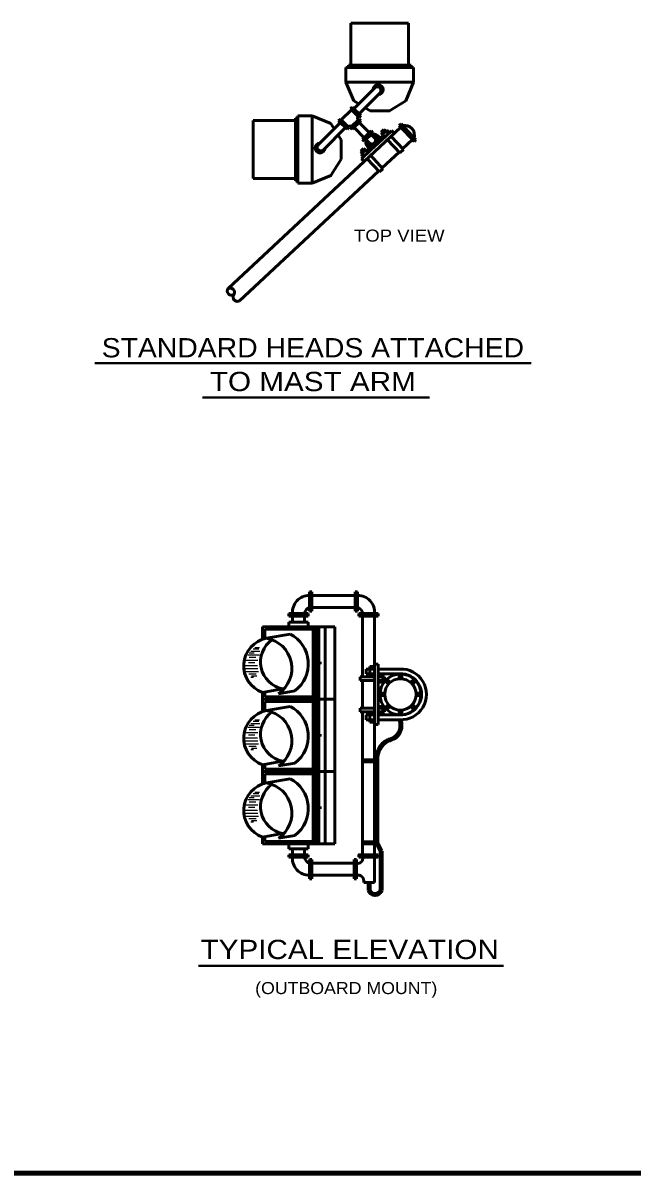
# Model space of a CAD drawing. Extents: x -370 to 486, y -203 to 341.
# Drawn here: x -43.9 to 107.7, y -191.2 to 95.1 of the extents above; entities that cross this region are included whole.
import ezdxf
from ezdxf.enums import TextEntityAlignment as Align

# ---------------------------------------------------------------- set-up
doc = ezdxf.new("R2010")
doc.units = 0
doc.header["$LTSCALE"] = 0.96
doc.layers.add('1', color=7, linetype='Continuous', lineweight=53)

msp = doc.modelspace()

# ---------------------------------------------------------------- linework, layer by layer
at = {"layer": '1'}
for p, q in [((37.6829, 95.0558), (37.6829, 84.5558)), ((37.6829, 95.0558), (52.0829, 95.0558)), ((52.0829, 95.0558), (52.0829, 84.5558)), ((36.4829, 83.9558), (53.2829, 83.9558)), ((36.4829, 83.9558), (36.4829, 80.3558)), ((37.0829, 84.5558), (52.6829, 84.5558)), ((37.0829, 84.5558), (37.0829, 83.9558)), ((52.6829, 84.5558), (52.6829, 83.9558)), ((53.2829, 83.9558), (53.2829, 80.3558)), ((36.4829, 80.3558), (53.2829, 80.3558)), ((38.4123, 75.6994), (36.4829, 80.3558)), ((51.3535, 75.6994), (53.2829, 80.3558)), ((43.6829, 78.9279), (38.4695, 73.688)), ((44.9587, 77.6586), (39.7453, 72.4184)), ((39.6816, 74.9063), (38.4123, 75.6994)), ((24.4829, 55.1558), (24.4829, 71.9558)), ((24.4829, 71.9558), (28.0829, 71.9558)), ((28.0829, 55.1558), (28.0829, 71.9558)), ((32.7392, 70.0263), (28.0829, 71.9558)), ((37.8336, 73.4744), (35.2946, 70.9223)), ((38.044, 74.1114), (37.6209, 73.686)), ((39.7474, 71.5699), (37.6209, 73.686)), ((40.1706, 71.9953), (38.044, 74.1114)), ((40.1706, 71.9953), (39.7474, 71.5699)), ((42.4829, 73.1558), (41.2472, 73.928)), ((13.3828, 56.3557), (13.3829, 70.7558)), ((13.3829, 70.7558), (23.8829, 70.7558)), ((23.8829, 55.7558), (23.8828, 71.3557)), ((23.8828, 71.3557), (24.4829, 71.3557)), ((35.0843, 70.2853), (29.5829, 64.7558)), ((36.36, 69.0156), (30.8587, 63.4862)), ((33.5445, 68.7377), (32.7392, 70.0263)), ((35.0817, 71.1342), (34.6585, 70.709)), ((36.7849, 68.5928), (34.6585, 70.709)), ((37.2081, 69.0181), (35.0817, 71.1342)), ((36.7849, 68.5928), (37.2081, 69.0181)), ((39.7485, 71.1458), (37.6325, 69.0189)), ((37.6325, 69.0189), (38.0578, 68.5958)), ((40.1738, 70.7227), (38.0578, 68.5958)), ((38.4809, 69.0211), (41.033, 66.4821)), ((39.7485, 71.1458), (40.1738, 70.7227)), ((39.7506, 70.2975), (42.3028, 67.7585)), ((50.1533, 69.0996), (41.0165, 60.5794)), ((50.183, 69.9476), (49.7442, 69.5384)), ((49.7442, 69.5384), (53.4269, 65.589)), ((50.183, 69.9476), (53.8657, 65.9982)), ((35.2829, 65.9558), (34.524, 67.1702)), ((35.2829, 61.1558), (35.2829, 65.9558)), ((42.7259, 68.1836), (40.6099, 66.0567)), ((40.6099, 66.0567), (41.0352, 65.6336)), ((43.1512, 67.7605), (41.0352, 65.6336)), ((41.4583, 66.0589), (42.345, 65.1769)), ((42.7259, 68.1836), (43.1512, 67.7605)), ((42.7282, 67.3353), (43.5787, 66.4892)), ((44.0623, 66.5011), (44.9781, 65.5902)), ((44.4379, 66.9738), (45.4172, 65.9997)), ((45.2662, 67.9102), (45.9243, 68.5241)), ((45.2662, 67.9102), (45.6755, 67.4712)), ((45.3463, 67.1644), (45.9601, 66.5061)), ((46.6628, 68.3919), (45.3464, 67.1643)), ((45.4708, 67.6909), (46.1289, 68.3048)), ((45.5657, 67.369), (46.1796, 66.7106)), ((45.5877, 68.0053), (45.8072, 68.21)), ((45.7924, 67.7861), (46.0119, 67.9907)), ((45.9243, 68.5241), (46.3337, 68.085)), ((46.4433, 68.1874), (47.0572, 67.529)), ((46.6628, 68.3919), (47.2766, 67.7336)), ((46.8362, 66.0064), (49.905, 62.715)), ((47.7139, 66.8248), (50.7826, 63.5334)), ((47.8412, 68.2601), (48.5243, 67.5805)), ((53.0178, 66.0278), (50.5781, 63.7528)), ((53.8657, 65.9982), (53.4269, 65.589)), ((40.182, 63.1691), (40.8401, 63.783)), ((40.182, 63.1691), (40.5913, 62.7301)), ((41.5786, 63.6508), (40.2622, 62.4232)), ((42.7085, 63.4738), (40.3598, 61.2836)), ((40.3866, 62.9498), (41.0447, 63.5637)), ((40.5035, 63.2642), (40.723, 63.4689)), ((40.7082, 63.045), (40.9277, 63.2496)), ((40.8401, 63.783), (41.2495, 63.3439)), ((41.3591, 63.4463), (41.973, 62.7879)), ((41.5786, 63.6508), (42.1924, 62.9925)), ((41.8508, 64.3269), (42.7085, 63.4738)), ((42.274, 64.7522), (43.1249, 63.9058)), ((50.7826, 63.5334), (49.905, 62.715)), ((41.0166, 60.5793), (7.1499, 28.9979)), ((40.2621, 62.4233), (40.8759, 61.765)), ((40.3474, 61.272), (41.0306, 60.5924)), ((40.4815, 62.6279), (41.0954, 61.9695)), ((41.752, 61.2653), (44.8208, 57.9739)), ((42.6296, 62.0836), (45.6984, 58.7922)), ((49.7005, 62.9343), (45.4939, 59.0116)), ((44.6163, 58.1933), (10.0142, 25.9263)), ((45.6984, 58.7922), (44.8208, 57.9739)), ((13.3828, 56.3557), (23.8828, 56.3557)), ((23.8829, 55.7558), (24.4829, 55.7557)), ((24.4829, 55.1558), (28.0829, 55.1558)), ((27.3912, -51.3342), (27.3912, -46.5342)), ((27.3912, -46.5342), (27.9912, -46.5342)), ((27.9912, -51.3342), (27.9912, -46.5342)), ((27.9912, -47.4342), (38.7912, -47.4342)), ((38.7912, -51.3342), (38.7912, -46.5342)), ((38.7912, -51.3342), (38.7912, -46.5342)), ((38.7912, -46.5342), (39.3912, -46.5342)), ((39.3912, -51.3342), (39.3912, -46.5342)), ((27.3912, -51.3342), (27.9912, -51.3342)), ((27.9912, -50.4342), (38.7912, -50.4342)), ((38.7912, -51.3342), (39.3912, -51.3342)), ((22.2912, -51.9342), (27.0912, -51.9342)), ((22.2912, -51.9342), (22.2912, -52.5342)), ((22.2912, -52.5342), (27.0912, -52.5342)), ((22.2912, -54.0342), (27.0912, -54.0342)), ((22.2912, -54.0342), (22.2912, -55.2342)), ((23.1912, -52.5342), (23.1912, -54.0342)), ((26.1912, -52.5342), (26.1912, -54.0342)), ((27.0912, -51.9342), (27.0912, -52.5342)), ((27.0912, -54.0342), (27.0912, -55.2342)), ((44.4912, -51.9342), (39.6912, -51.9342)), ((39.6912, -51.9342), (39.6912, -52.5342)), ((44.4912, -52.5342), (39.6912, -52.5342)), ((40.5912, -52.5342), (40.5912, -67.6542)), ((44.4912, -51.9342), (44.4912, -52.5342)), ((15.6912, -55.2342), (33.6912, -55.2342)), ((15.6912, -55.2342), (15.6912, -58.3133)), ((16.2912, -55.8342), (28.8912, -55.8342)), ((16.2912, -55.8342), (16.2912, -58.153)), ((22.5912, -57.0342), (16.6824, -58.0761)), ((28.2912, -55.8342), (28.2912, -72.6342)), ((28.8912, -55.8342), (28.8912, -72.6342)), ((31.2912, -55.2342), (31.2912, -109.2342)), ((33.6912, -55.2342), (33.6912, -109.2342)), ((30.0912, -63.9342), (28.8912, -63.9342)), ((30.0912, -64.5342), (28.8912, -64.5342)), ((30.0912, -63.9342), (30.0912, -64.5342)), ((41.4912, -65.7342), (41.4912, -66.9342)), ((41.4912, -65.7342), (43.5912, -65.7342)), ((42.3912, -65.1342), (43.5912, -65.1342)), ((42.3912, -65.1342), (42.3912, -67.5342)), ((43.5912, -64.5342), (44.4912, -64.5342)), ((44.4912, -64.5342), (44.4912, -79.5342)), ((44.4912, -65.7342), (49.8912, -65.7342)), ((39.9912, -67.6542), (43.5912, -67.6542)), ((39.9912, -67.6542), (39.9912, -68.6142)), ((39.9912, -68.6142), (43.5912, -68.6142)), ((40.5912, -68.6142), (40.5912, -75.4542)), ((41.4912, -66.9342), (43.5912, -66.9342)), ((42.3912, -67.5342), (43.5912, -67.5342)), ((44.4912, -66.9342), (49.8912, -66.9342)), ((44.4912, -67.2342), (45.6912, -67.2342)), ((44.4912, -67.6542), (46.1112, -67.6542)), ((44.4912, -68.6142), (46.1112, -68.6142)), ((45.6912, -67.2342), (45.6912, -69.0342)), ((46.1112, -67.6542), (46.1112, -68.6142)), ((47.0679, -69.4743), (46.2421, -68.6486)), ((47.4922, -69.05), (46.6664, -68.2243)), ((49.7516, -68.133), (49.7516, -66.9596)), ((50.3516, -68.133), (50.3516, -66.9596)), ((52.5785, -69.07), (53.4294, -68.2238)), ((53.0016, -69.4955), (53.8525, -68.6493)), ((20.6964, -70.6569), (15.6912, -71.5394)), ((15.6912, -73.2342), (15.6912, -71.5394)), ((16.2912, -72.6342), (16.2912, -71.4336)), ((23.7912, -71.1342), (19.655, -71.8635)), ((44.4912, -69.0342), (45.6912, -69.0342)), ((15.6912, -73.2342), (33.6912, -73.2342)), ((15.6912, -73.2342), (15.6912, -76.3442)), ((16.2912, -72.6342), (28.8912, -72.6342)), ((16.2912, -73.8342), (28.8912, -73.8342)), ((16.2912, -73.8342), (16.2912, -76.1633)), ((28.2912, -73.8342), (28.2912, -90.6342)), ((28.8912, -73.8342), (28.8912, -90.6342)), ((44.9517, -71.7342), (46.1248, -71.7342)), ((44.9517, -72.3342), (46.1248, -72.3342)), ((53.9248, -71.7342), (55.1515, -71.7342)), ((53.9248, -72.3342), (55.1515, -72.3342)), ((22.5912, -75.0342), (16.6824, -76.0761)), ((39.9912, -75.4542), (43.5912, -75.4542)), ((39.9912, -75.4542), (39.9912, -76.4142)), ((39.9912, -76.4142), (43.5912, -76.4142)), ((40.5912, -76.4142), (40.5912, -111.9598)), ((41.4912, -77.1342), (41.4912, -78.3342)), ((41.4912, -77.1342), (43.5912, -77.1342)), ((42.3912, -76.5342), (42.3912, -78.9342)), ((42.3912, -76.5342), (43.5912, -76.5342)), ((44.4912, -75.0342), (45.6912, -75.0342)), ((44.4912, -75.4542), (46.1112, -75.4542)), ((44.4912, -76.4142), (46.1112, -76.4142)), ((44.4912, -76.8342), (45.6912, -76.8342)), ((44.4912, -77.1342), (49.8912, -77.1342)), ((45.6912, -75.0342), (45.6912, -76.8342)), ((46.1112, -75.4542), (46.1112, -76.4142)), ((46.1972, -75.4162), (47.0479, -74.5702)), ((46.6203, -75.8417), (47.471, -74.9957)), ((49.7516, -77.1596), (49.7516, -75.9328)), ((50.3516, -77.1596), (50.3516, -75.9328)), ((53.4595, -75.8641), (52.5841, -74.989)), ((53.8836, -75.4398), (53.0082, -74.5647)), ((41.4912, -78.3342), (43.5912, -78.3342)), ((42.3912, -78.9342), (43.5912, -78.9342)), ((43.5912, -79.5342), (44.4912, -79.5342)), ((44.4912, -78.3342), (49.8912, -78.3342)), ((30.0912, -81.9342), (28.8912, -81.9342)), ((30.0912, -82.5342), (28.8912, -82.5342)), ((30.0912, -81.9342), (30.0912, -82.5342)), ((20.6964, -88.6569), (15.6912, -89.5394)), ((15.6912, -91.2342), (15.6912, -89.5394)), ((15.6912, -91.2342), (33.6912, -91.2342)), ((15.6912, -91.2342), (15.6912, -94.3442)), ((16.2912, -90.6342), (16.2912, -89.4336)), ((16.2912, -90.6342), (28.8912, -90.6342)), ((23.7912, -89.1342), (19.655, -89.8635)), ((16.2912, -91.8342), (28.8912, -91.8342)), ((16.2912, -91.8342), (16.2912, -94.1633)), ((22.5912, -93.0342), (16.6824, -94.0761)), ((28.2912, -91.8342), (28.2912, -108.6342)), ((28.8912, -91.8342), (28.8912, -108.6342)), ((30.0912, -99.9342), (28.8912, -99.9342)), ((30.0912, -99.9342), (30.0912, -100.5342)), ((30.0912, -100.5342), (28.8912, -100.5342)), ((20.6964, -106.6569), (15.6912, -107.5394)), ((15.6912, -109.2342), (15.6912, -107.5394)), ((16.2912, -108.6342), (16.2912, -107.4336)), ((16.2912, -108.6342), (28.8912, -108.6342)), ((23.7912, -107.1342), (19.655, -107.8635)), ((15.6912, -109.2342), (33.6912, -109.2342)), ((22.2912, -110.4594), (22.2912, -109.2594)), ((22.2912, -110.4594), (27.0912, -110.4594)), ((23.1912, -111.9594), (23.1912, -110.4594)), ((26.1912, -111.9594), (26.1912, -110.4594)), ((27.0912, -110.4594), (27.0912, -109.2594)), ((22.2912, -111.9594), (27.0912, -111.9594)), ((22.2912, -112.5594), (22.2912, -111.9594)), ((22.2912, -112.5594), (27.0912, -112.5594)), ((27.0912, -112.5594), (27.0912, -111.9594)), ((27.3912, -113.1594), (27.3912, -117.9594)), ((27.3912, -113.1594), (27.9912, -113.1594)), ((27.9912, -113.1594), (27.9912, -117.9594)), ((27.9912, -114.0594), (38.4908, -114.0594)), ((38.4908, -113.1592), (38.4908, -117.9592)), ((38.4908, -113.1592), (39.0908, -113.1592)), ((39.0908, -113.1592), (39.0908, -117.9592)), ((44.4908, -112.5625), (39.6908, -112.5592)), ((43.5908, -112.5619), (43.5866, -118.8617)), ((44.4912, -111.9626), (44.4908, -112.5625)), ((27.9912, -117.0594), (38.4908, -117.0594)), ((27.3912, -117.9594), (27.9912, -117.9594)), ((38.4908, -117.9592), (39.0908, -117.9592)), ((43.5866, -118.8617), (40.8866, -118.8617))]:
    msp.add_line(p, q, dxfattribs=at)
at = {"layer": '1', "lineweight": 40}
for p, q in [((-26.0644, 10.3957), (82.5751, 10.3957)), ((0.7937, 1.8805), (57.2808, 1.8805)), ((-0.2193, -139.639), (75.6541, -139.639))]:
    msp.add_line(p, q, dxfattribs=at)
at = {"layer": '1', "lineweight": 90}
for p, q in [((29.4912, -55.2342), (29.4912, -63.9342)), ((29.4912, -64.5342), (29.4912, -81.9342)), ((29.4912, -82.5342), (29.4912, -99.9342)), ((29.4912, -100.5342), (29.4912, -109.2342))]:
    msp.add_line(p, q, dxfattribs=at)
at = {"layer": '1', "lineweight": 25}
for p, q in [((12.0671, -62.204), (14.9201, -62.204)), ((12.3588, -61.6933), (13.6373, -61.6933)), ((12.3953, -62.7877), (14.0733, -62.7877)), ((12.7964, -61.292), (15.0719, -61.292)), ((13.4164, -60.6718), (14.81, -60.6718)), ((13.8176, -60.38), (14.9534, -60.38)), ((11.3012, -65.5968), (14.5107, -65.5968)), ((11.4106, -64.8672), (14.4396, -64.8672)), ((11.4471, -63.5174), (14.5504, -63.5174)), ((12.2129, -64.1375), (13.818, -64.1375)), ((11.3012, -66.3629), (14.6803, -66.3629)), ((12.2998, -66.9315), (14.1149, -66.9315)), ((12.7748, -67.7631), (13.4875, -67.7631)), ((12.9827, -67.4364), (14.3242, -67.4364)), ((12.3588, -79.6933), (13.6373, -79.6933)), ((12.7964, -79.292), (15.0719, -79.292)), ((13.4164, -78.6718), (14.81, -78.6718)), ((13.8176, -78.38), (14.9534, -78.38)), ((11.4106, -82.8672), (14.4396, -82.8672)), ((11.4471, -81.5174), (14.5504, -81.5174)), ((12.0671, -80.204), (14.9201, -80.204)), ((12.2129, -82.1375), (13.818, -82.1375)), ((12.3953, -80.7877), (14.0733, -80.7877)), ((11.3012, -83.5968), (14.5107, -83.5968)), ((11.3012, -84.3629), (14.6803, -84.3629)), ((12.2998, -84.9315), (14.1149, -84.9315)), ((12.7748, -85.7631), (13.4875, -85.7631)), ((12.9827, -85.4364), (14.3242, -85.4364)), ((12.7964, -97.292), (15.0719, -97.292)), ((13.4164, -96.6718), (14.81, -96.6718)), ((13.8176, -96.38), (14.9534, -96.38)), ((11.4471, -99.5174), (14.5504, -99.5174)), ((12.0671, -98.204), (14.9201, -98.204)), ((12.2129, -100.1375), (13.818, -100.1375)), ((12.3588, -97.6933), (13.6373, -97.6933)), ((12.3953, -98.7877), (14.0733, -98.7877)), ((11.3012, -101.5968), (14.5107, -101.5968)), ((11.3012, -102.3629), (14.6803, -102.3629)), ((11.4106, -100.8672), (14.4396, -100.8672)), ((12.2998, -102.9315), (14.1149, -102.9315)), ((12.7748, -103.7631), (13.4875, -103.7631)), ((12.9827, -103.4364), (14.3242, -103.4364))]:
    msp.add_line(p, q, dxfattribs=at)
at = {"layer": '1', "lineweight": 158}
for p, q in [((44.1912, -88.5624), (40.6061, -88.5598)), ((44.1914, -108.9624), (40.5912, -108.9598)), ((479.406, -191.1602), (-312.194, -191.1602))]:
    msp.add_line(p, q, dxfattribs=at)
at = {"layer": '1', "lineweight": 106}
for p, q in [((45.2366, -120.6617), (45.2366, -111.0617)), ((42.2366, -120.6617), (42.2366, -118.8617))]:
    msp.add_line(p, q, dxfattribs=at)
at = {"layer": '1'}
for points in [[(42.4829, 73.1558), (47.2829, 73.1558), (51.3535, 75.6994)], [(47.8195, 68.2399), (45.4172, 65.9997), (42.7085, 63.4738)], [(35.2829, 61.1558), (32.7392, 57.0851), (28.0829, 55.1558)], [(43.5912, -52.5342), (43.5912, -88.562), (43.5912, -108.962), (43.5912, -111.962)], [(44.4912, -111.9626), (39.6912, -111.9592), (39.6908, -112.5592)]]:
    msp.add_lwpolyline(points, dxfattribs=at)
at = {"layer": '1', "lineweight": 106}
msp.add_lwpolyline([(44.1912, -88.562), (44.1912, -108.962), (45.2366, -111.0617)], dxfattribs=at)
at = {"layer": '1'}
for centre, radius in [((50.0516, -72.0596), 5.1), ((50.0248, -72.0329), 3.9)]:
    msp.add_circle(centre, radius, dxfattribs=at)
for centre, radius, start, end in [((44.5022, 78.4756), 1.2428, 271.53559, 178.75707), ((44.3209, 78.2934), 0.8998, 315.13282, 135.15983), ((39.9285, 71.3562), 0.5795, 132.78877, 226.89174), ((37.4209, 68.8356), 0.5795, 43.09034, 137.19331), ((51.0827, 67.0948), 2.4634, 344.51342, 101.48659), ((42.9025, 65.4258), 1.521, 157.40371, 226.25762), ((43.1497, 65.6575), 1.2428, 182.10453, 89.27128), ((42.9625, 65.8335), 0.8998, 226.74884, 46.77586), ((43.3546, 65.9061), 1.521, 44.58462, 113.43853), ((30.0394, 63.9387), 1.2428, 91.53442, 358.7447), ((30.2208, 64.121), 0.8999, 135.13507, 315.14405), ((8.0131, 28.3672), 1.069, 143.84232, 302.15542), ((7.675, 28.0278), 1.069, 328.05031, 126.36341), ((9.4452, 26.8314), 1.069, 143.84232, 302.15542), ((27.314, -51.5721), 4.1387, 88.93093, 185.01894), ((39.4684, -51.5721), 4.1387, 354.98106, 91.06907), ((27.8585, -52.0381), 1.6706, 106.24508, 176.43531), ((38.9239, -52.0381), 1.6706, 3.56469, 73.75492), ((18.7112, -64.4655), 8.3832, 307.29917, 62.42986), ((18.0077, -64.9418), 6.9925, 100.9259, 250.65279), ((22.0002, -63.9848), 6.7983, 125.42652, 258.94304), ((15.4143, -65.5637), 7.5942, 303.94628, 80.38748), ((50.1844, -72.0342), 6.3068, 267.33556, 92.66444), ((50.1829, -72.0342), 5.1083, 266.72684, 93.27315), ((18.0077, -82.9418), 6.9925, 100.9259, 250.65279), ((22.0002, -81.9848), 6.7983, 125.42652, 258.94304), ((15.4143, -83.5637), 7.5942, 303.94628, 80.38748), ((18.7112, -82.4655), 8.3832, 307.29917, 62.42986), ((18.0077, -100.9418), 6.9925, 100.9259, 250.65279), ((22.0002, -99.9848), 6.7983, 125.42652, 258.94304), ((15.4143, -101.5637), 7.5942, 303.94628, 80.38748), ((18.7112, -100.4655), 8.3832, 307.29917, 62.42986), ((27.314, -112.9215), 4.1387, 174.98106, 271.06907), ((27.8585, -112.4555), 1.6706, 183.56469, 253.75492), ((39.4382, -112.9068), 1.2036, 253.22176, 16.76297), ((39.4426, -118.5045), 1.4875, 346.10771, 103.67892)]:
    msp.add_arc(centre, radius, start, end, dxfattribs=at)
at = {"layer": '1', "lineweight": 106}
for centre, radius, start, end in [((46.4402, -79.7668), 3.7365, 279.16279, 22.54388), ((49.2, -88.0065), 5.0395, 115.43994, 186.32898), ((43.7366, -120.3242), 1.5375, 192.68038, 347.31962)]:
    msp.add_arc(centre, radius, start, end, dxfattribs=at)

# ---------------------------------------------------------------- texts
at = {"layer": '1'}
for s, height, width, p in [('TOP VIEW', 3, 1.15, (49.7507, 40.6394)), ('STANDARD HEADS ATTACHED', 4.8, 1.1, (28.2334, 11.8317)), ('TO MAST ARM', 4.8, 1.15, (28.2334, 3.4317)), ('TYPICAL ELEVATION', 4.8, 1.15, (37.4049, -137.9213)), ('(OUTBOARD MOUNT)', 3, 1.1, (36.5459, -146.6345))]:
    msp.add_text(s, height=height, dxfattribs=dict(at, width=width)).set_placement(p, align=Align.CENTER)

doc.saveas('drawing.dxf')
